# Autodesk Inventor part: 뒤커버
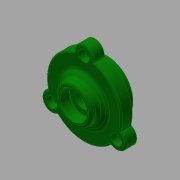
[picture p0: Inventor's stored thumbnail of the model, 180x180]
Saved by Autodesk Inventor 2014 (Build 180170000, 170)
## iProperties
Created: 2016-05
Part Number: 뒤커버
Document SubType Name: Modeling
Designer: mduedu
Density: 2.71 g/cm^3
Material: 알루미늄 6061
Appearance: 진녹색
Author: mduedu
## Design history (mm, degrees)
sketch "스케치1"
  geometry: C1 r 20 at (0, 0); C2 r 27.5 at (0, 0); 1 further point
  constraints: 2 centre point, 2 coincident
  dimensions: "d33" = 55 diameter of C2; "d34" = 40 diameter of C1
extrude "돌출1" new body sketch "스케치1" distance "d0" = 8; taper "d1" = 0 deg
extrude "돌출2" join sketch "스케치1" distance "d2" = 8; taper "d3" = 0 deg; dims "d35" = 9, "d36" = 0
sketch "스케치5"
  geometry: L1 (-27.5, 8)-(27.5, 8) reference; L2 (0, 0)-(0, 15); L3 (-27.5, 0)-(27.5, 0) reference; L4 (17.5, 8)-(0, 8); A1 r 25.375 centre (0, -10.375) between (17.5, 8) and (0, 15)
  constraints: 4 end point, 3 point on line, 2 point on circle, 1 centre point, 1 midpoint, 1 perpendicular
  dimensions: "d37" = 17.5 distance from line of L2 L4.start; "d39" = 7 distance from line of L1 L2.end
revolve "회전2" sketch "스케치5" stored, may be unused: angle "d40" = 90 deg
node "작업 평면1"
sketch "스케치6"
  geometry: C1 r 13.5 at (0, 0); 1 further point
  constraints: 1 centre point, 1 coincident
  dimensions: "d42" = 27 diameter of C1
extrude "돌출4" join sketch "스케치6" stored distance "d43" = 10; taper "d44" = 0 deg
sketch "스케치4"
  geometry: L1 (0, -9)-(0, 16); L2 (-15, -9)-(-15, 0); L3 (-15, 0)-(-10, 0); L4 (-10, 0)-(-10, 3); L5 (-10, 3)-(-6, 3); L6 (-6, 3)-(-6, 8.6); L7 (-6, 8.6)-(-10, 8.6); L8 (-10, 8.6)-(-10, 16); L9 (20, -9)-(-20, -9) reference; L10 (-13.5, 16)-(13.5, 16) reference; 1 further point
  constraints: 16 end point, 6 parallel, 3 point on line, 2 midpoint, 1 perpendicular, 1 vertical
  dimensions: "d15" = 30 diameter of L2 L1; "d16" = 20 diameter of L8 L1; "d18" = 9 distance of L2.start L2.end; "d19" = 3 distance of L3.end L4.end; "d20" = 20 diameter of L4 L1; "d21" = 12 diameter of L6 L1; "d45" = 7.4 distance of L7.end L8.end
revolve "회전1" sketch "스케치4" stored, may be unused: angle "d22" = 90 deg
fillet "모깎기2" dims "d23" = 3
fillet "모깎기3" dims "d24" = 0.3
chamfer "모따기2" distance "d46" = 1; stored, may be unused: second distance "d47" = 2, angle "d48" = 45 deg
fillet "모깎기4" dims "d49" = 3
fillet "모깎기5" dims "d50" = 2
sketch "스케치7"
  geometry: C1 r 7 at (0, 27.5); 2 further points
  constraints: 3 vertical alignment, 1 centre point, 2 other
  dimensions: "d54" = 14 diameter of C1
extrude "돌출5" join sketch "스케치7" stored distance "d55" = 10; taper "d56" = 0 deg
fillet "모깎기6" dims "d57" = 1
fillet "모깎기7" dims "d61" = 1
sketch "스케치8" dims "d62" = 55 (derived)
  geometry: C1 r 18.661 at (0, 0) reference; A1 r 2 centre (-7.999, 27.355) between (-7.437, 25.435) and (-5.999, 27.391) reference; A2 r 26.5 centre (0, 0) between (-7.437, 25.435) and (-25.746, -6.277) reference; A3 r 2 centre (-27.689, -6.75) between (-26.721, -8.5) and (-25.746, -6.277) reference; A4 r 6 centre (-23.816, -13.75) between (-26.721, -8.5) and (-20.722, -18.891) reference; A5 r 2 centre (-19.69, -20.604) between (-18.309, -19.158) and (-20.722, -18.891) reference; A6 r 26.5 centre (0, 0) between (-18.309, -19.158) and (18.309, -19.158) reference; A7 r 2 centre (19.69, -20.604) between (20.722, -18.891) and (18.309, -19.158) reference; A8 r 6 centre (23.816, -13.75) between (20.722, -18.891) and (26.721, -8.5) reference; A9 r 2 centre (27.689, -6.75) between (25.746, -6.277) and (26.721, -8.5) reference; A10 r 26.5 centre (0, 0) between (25.746, -6.277) and (7.437, 25.435) reference; A11 r 2 centre (7.999, 27.355) between (5.999, 27.391) and (7.437, 25.435) reference; A12 r 6 centre (0, 27.5) between (5.999, 27.391) and (-5.999, 27.391) reference; 4 further points
  constraints: 2 coincident, 1 vertical alignment, 6 other
  dimensions: "d65" = 360 deg dimension on A2.centre point (0, 27.5) (derived)
sketch "스케치9"
  geometry: 3 further points
  constraints: 3 other
hole "구멍2" sketch "스케치9" at (-23.816, -13.75), (23.816, -13.75), (0, 27.5) diameter "d67" = 4.5; stored, may be unused: countersink angle "d71" = 90 deg, drill point angle "d73" = 0 deg; dims "d68" = 6, "d69" = 8, "d70" = 4.6, "d72" = 8
chamfer "모따기3" distance "d76" = 0.7; stored, may be unused: second distance "d77" = 2, angle "d78" = 30 deg
node "솔리드1"
pattern_circular "원형 패턴1" dims angle "d59" = 360 deg
other parameters: "d41" = 8
